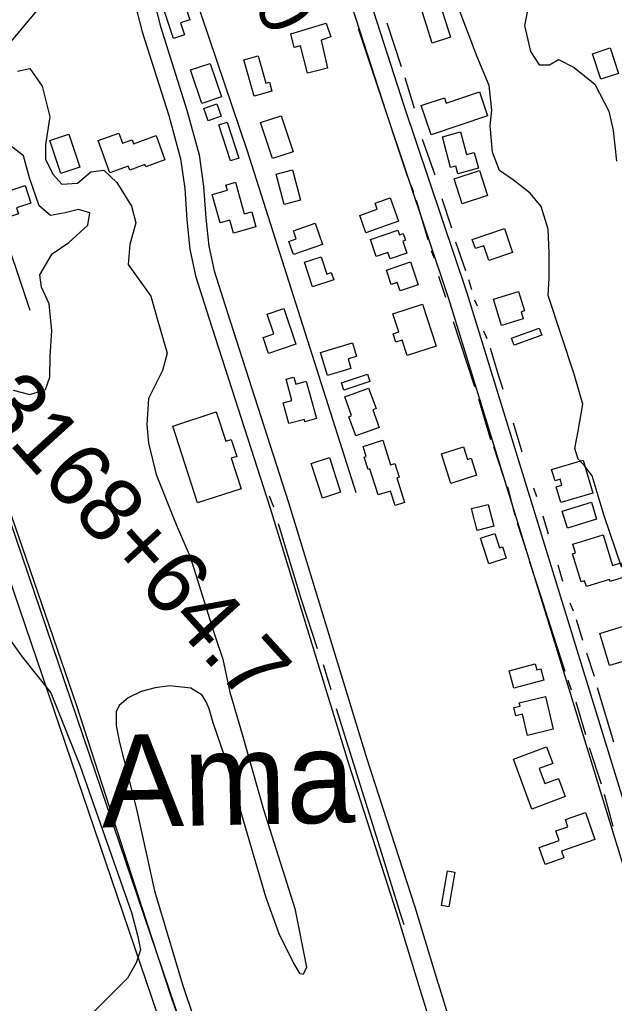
# Model space of a CAD drawing. Extents: x 3598634 to 3636690, y 517270 to 542944.
# Drawn here: x 3608244 to 3609179, y 527023 to 528569 of the extents above; entities that cross this region are included whole.
import ezdxf

# ---------------------------------------------------------------- set-up
doc = ezdxf.new("R2010")
doc.units = 0
for name, color, linetype in [('V-BLDG-OTLN', 7, 'Continuous'), ('V-RIVR-RANG-IDEN', 7, 'Continuous'), ('V-ROAD-CNTR', 7, 'Continuous'), ('V-SITE-VEGE', 7, 'Continuous'), ('V-SURV-IDEN', 7, 'Continuous'), ('V-TOPO-GNAM-IDEN', 7, 'Continuous'), ('V-TOPO-SHOR', 7, 'Continuous')]:
    doc.layers.add(name, color=color, linetype=linetype)

msp = doc.modelspace()

# ---------------------------------------------------------------- linework, layer by layer
at = {"layer": 'V-BLDG-OTLN'}
for points in [[(3608489.2, 528634.6), (3608511.4, 528568.5), (3608496.9, 528563.6), (3608503.1, 528545), (3608485.9, 528539.2), (3608455.8, 528628.5), (3608475.9, 528635.3), (3608477.5, 528630.7)], [(3608892.4, 528531.9), (3608871.5, 528598), (3608900.1, 528607), (3608921, 528540.9)], [(3608696.3, 528484.4), (3608685.5, 528527.3), (3608675.5, 528524.8), (3608670.1, 528546.1), (3608725.8, 528563.3), (3608733.2, 528541.5), (3608717.9, 528536.6), (3608728, 528492.4)], [(3609157.8, 528474.9), (3609144.3, 528515.1), (3609172, 528524.4), (3609185.5, 528484.2)], [(3608618.8, 528511.7), (3608631, 528468.8), (3608636.4, 528470.3), (3608640.4, 528456), (3608612.7, 528448.2), (3608596.5, 528505.4)], [(3608530.1, 528437.1), (3608512.6, 528489.5), (3608543.4, 528499.8), (3608560.9, 528447.4)], [(3608979.2, 528417.3), (3608890.7, 528387.6), (3608875.3, 528433.5), (3608911.8, 528445.8), (3608914.5, 528437.6), (3608966.6, 528455.1)], [(3608560.7, 528417.2), (3608540.3, 528409.8), (3608533.3, 528428.9), (3608553.8, 528436.4)], [(3608641.5, 528350.3), (3608622.6, 528406.8), (3608654.9, 528417.6), (3608673.8, 528361.1)], [(3608570.2, 528407.7), (3608588.4, 528351.1), (3608575.1, 528346.8), (3608556.9, 528403.4)], [(3608321, 528388.7), (3608338.6, 528336.8), (3608308.8, 528326.7), (3608291.2, 528378.6)], [(3608472, 528348.1), (3608442, 528337.2), (3608440.7, 528340.9), (3608416.8, 528332.3), (3608414.6, 528338.2), (3608385.6, 528327.7), (3608367.2, 528378.7), (3608399.6, 528390.4), (3608405.4, 528374.4), (3608420.5, 528379.8), (3608422.6, 528373.7), (3608458.2, 528386.5)], [(3608937, 528392.2), (3608946.4, 528356.8), (3608958.5, 528360), (3608965.1, 528335.2), (3608932.6, 528326.6), (3608929.4, 528338.5), (3608921.4, 528336.4), (3608908.5, 528384.7)], [(3608659.7, 528278.1), (3608646.9, 528325.8), (3608672.6, 528332.7), (3608685.4, 528285)], [(3608979.6, 528292.1), (3608939.4, 528279.2), (3608926.8, 528318.6), (3608967, 528331.4)], [(3608220.9, 528256.5), (3608208.1, 528296.9), (3608229.7, 528303.8), (3608230.6, 528300.9), (3608252.4, 528307.9), (3608261.3, 528280.1), (3608238.9, 528273), (3608242, 528263.3)], [(3608582.9, 528313), (3608597, 528263.3), (3608608.6, 528266.6), (3608615.3, 528243.3), (3608580.2, 528233.3), (3608574.4, 528253.8), (3608559, 528249.4), (3608546.4, 528293.7), (3608570.4, 528300.6), (3608568, 528308.8)], [(3608839.3, 528251.9), (3608788.2, 528233.7), (3608778.5, 528260.9), (3608805.8, 528270.7), (3608802.5, 528280), (3608826.2, 528288.5)], [(3608708.6, 528248.7), (3608720.1, 528215.3), (3608674.2, 528199.5), (3608667.1, 528220.2), (3608678.8, 528224.2), (3608674.5, 528236.9)], [(3608795.6, 528223.4), (3608838.5, 528237.6), (3608840.9, 528230.4), (3608847, 528232.5), (3608850.5, 528221.9), (3608846.5, 528220.5), (3608852.7, 528201.5), (3608826.2, 528192.7), (3608822.9, 528202.5), (3608804.5, 528196.5)], [(3608955.5, 528223.4), (3609006, 528240.3), (3609018.6, 528202.5), (3608981.3, 528190), (3608973.4, 528213.4), (3608960.3, 528209)], [(3608704.3, 528148.6), (3608691.4, 528187.5), (3608717.6, 528196.1), (3608726.6, 528168.7), (3608733.8, 528171.1), (3608737.6, 528159.6)], [(3608858.1, 528187.9), (3608870.3, 528151.8), (3608842.2, 528142.3), (3608837.6, 528155.7), (3608828.1, 528152.5), (3608820.5, 528175.2)], [(3609001.4, 528087.8), (3608988.6, 528129.4), (3609027.9, 528141.5), (3609037.3, 528111), (3609032.1, 528109.4), (3609035.6, 528098.3)], [(3608659.2, 528114.7), (3608678.1, 528058.8), (3608634.9, 528044.2), (3608626.4, 528069.4), (3608643.3, 528075.1), (3608632.9, 528105.8)], [(3608877, 528121.8), (3608898.6, 528055.7), (3608853, 528040.8), (3608845, 528065.2), (3608835.1, 528062), (3608830.8, 528075.2), (3608839.7, 528078.2), (3608830.5, 528106.6)], [(3609064.7, 528072.7), (3609021.1, 528057.1), (3609017.1, 528068.2), (3609060.7, 528083.8)], [(3608727.7, 528009.7), (3608716.9, 528045.8), (3608767, 528060.8), (3608773.4, 528039.5), (3608760.2, 528035.6), (3608764.6, 528020.7)], [(3608694.3, 528000.5), (3608710.4, 527941.9), (3608692.4, 527936.9), (3608691.4, 527940.6), (3608667.2, 527933.9), (3608658.2, 527966.7), (3608671.8, 527970.4), (3608662.6, 528003.5), (3608675, 528007), (3608678.1, 527996)], [(3608794.4, 528000), (3608753.5, 527986.5), (3608749.7, 527997.9), (3608790.6, 528011.4)], [(3608809.1, 527928), (3608772.3, 527914.5), (3608761.2, 527944.8), (3608765.8, 527946.5), (3608754.9, 527976.1), (3608792.2, 527989.8), (3608804.1, 527957.4), (3608799, 527955.5)], [(3608523.6, 527809.4), (3608484.4, 527930.1), (3608552.8, 527952.2), (3608567.7, 527906.3), (3608576.4, 527909.1), (3608585, 527882.4), (3608576.4, 527879.6), (3608591.9, 527831.6)], [(3608807.4, 527821.8), (3608794.6, 527862.7), (3608791.5, 527861.7), (3608785.4, 527881.2), (3608788.8, 527882.3), (3608783.8, 527898.1), (3608814.8, 527907.8), (3608827, 527869.1), (3608833.7, 527871.2), (3608840.4, 527850), (3608836.6, 527848.8), (3608848.9, 527809.7), (3608834.2, 527805.1), (3608827.1, 527828)], [(3608921.8, 527839.9), (3608907, 527886.2), (3608941.6, 527897.3), (3608947.9, 527877.7), (3608953.6, 527879.6), (3608962.2, 527852.8)], [(3608730.7, 527880.6), (3608748.2, 527826.1), (3608719.7, 527816.9), (3608702.2, 527871.4)], [(3609145, 527824.7), (3609094.6, 527809.8), (3609087.3, 527834.6), (3609096.2, 527837.2), (3609093.5, 527846.4), (3609085.5, 527844.1), (3609080.2, 527862), (3609129.7, 527876.6)], [(3608963.1, 527766.2), (3608954.4, 527800.3), (3608980.3, 527807), (3608989.1, 527772.9)], [(3609151, 527783.8), (3609105.4, 527769.6), (3609097, 527796.4), (3609142.7, 527810.6)], [(3608981.4, 527713.8), (3608968.5, 527754), (3608990.9, 527761.1), (3608998.1, 527738.6), (3609003, 527740.1), (3609008.7, 527722.5)], [(3609161.1, 527759.3), (3609176, 527710.9), (3609188.9, 527714.9), (3609195.7, 527692.9), (3609172.3, 527685.7), (3609171.3, 527689.2), (3609134.8, 527678), (3609132, 527687.1), (3609126.4, 527685.4), (3609112.8, 527729.5), (3609117.5, 527730.9), (3609113.3, 527744.6)], [(3609171.4, 527553.7), (3609155.9, 527604.1), (3609194.6, 527616), (3609210.1, 527565.6)], [(3609013.5, 527545.6), (3609054.4, 527556.3), (3609056.9, 527547.1), (3609063.1, 527548.7), (3609067.8, 527530.9), (3609020.7, 527518.4)], [(3609042.5, 527444.1), (3609034.5, 527477.4), (3609023.9, 527474.9), (3609020.8, 527487.7), (3609030.6, 527490.1), (3609029.4, 527495.4), (3609070.3, 527505.3), (3609082.7, 527453.8)], [(3609049, 527328.3), (3609020, 527406.7), (3609072.3, 527426.1), (3609081.9, 527400.1), (3609060.5, 527392.2), (3609069.3, 527368.4), (3609091, 527376.4), (3609101.5, 527347.8)], [(3609148.2, 527280.4), (3609095.8, 527262.2), (3609099.5, 527251.6), (3609069.8, 527241.3), (3609060.5, 527268.1), (3609091.9, 527279.1), (3609086.8, 527293.9), (3609105.8, 527300.5), (3609101.9, 527311.8), (3609133.5, 527322.8)], [(3608928.2, 527228.9), (3608918.6, 527174.7), (3608907, 527176.8), (3608916.6, 527231)]]:
    msp.add_lwpolyline(points, close=True, dxfattribs=at)
at = {"layer": 'V-ROAD-CNTR'}
for points in [[(3606832.7, 526952), (3606973.8, 527100.2), (3607148.9, 527293), (3607268.5, 527428.8), (3607385.5, 527558.8), (3607495.8, 527683.5), (3607551.8, 527751.4), (3607615.9, 527832.2), (3607705.6, 527929.3), (3607806.9, 528046.9), (3607941.6, 528200.2), (3608081.9, 528357.7), (3608279.1, 528592.5), (3608364.5, 528689.3), (3608525, 528869.3), (3608605.5, 528959.8), (3608701.5, 529074.5), (3608833.1, 529225.4), (3608919, 529316.1), (3609050.5, 529472.9), (3609139.7, 529575.2), (3609208.8, 529647.9)], [(3608665.2, 529018.6), (3608688, 528947.3), (3608746.2, 528749.1), (3608848.5, 528432), (3608946.8, 528139.6), (3609111.4, 527605.9), (3609243, 527178.6), (3609394.6, 526698), (3609572.4, 526137.8), (3609769.5, 525515.2), (3610214.2, 524114.9)], [(3608636.6, 529009.4), (3608659.4, 528938.5), (3608717.5, 528740.2), (3608820.1, 528422.7), (3608918.3, 528130.4), (3609082.7, 527597.1), (3609214.4, 527169.6), (3609366, 526689), (3609543.8, 526128.7), (3609740.9, 525506.2), (3610185.6, 524105.8)], [(3608466.5, 528803.7), (3608505.7, 528646.3), (3608601.7, 528362.3), (3608772.5, 527825.5)], [(3608387, 528725.9), (3608405.8, 528667.7), (3608436.5, 528549.6), (3608478.2, 528418.1), (3608496.5, 528349.9), (3608503.3, 528303.4), (3608506.7, 528254.2), (3608511.6, 528208.2), (3608520.5, 528166.1), (3608541.3, 528100.2), (3608637.9, 527800.8), (3608761.2, 527398.4), (3608836.5, 527165.4), (3608873.2, 527045.2)], [(3608415.5, 528735.2), (3608434.7, 528676.1), (3608465.4, 528557.9), (3608506.9, 528426.5), (3608526, 528356), (3608533.1, 528306.6), (3608536.6, 528256.8), (3608541.2, 528212.9), (3608549.6, 528173.8), (3608569.9, 528109.3), (3608666.5, 527809.8), (3608789.8, 527407.4), (3608865.1, 527174.4), (3608901.9, 527053.9)], [(3608142.4, 528423.1), (3608166, 528387.7), (3608205, 528272.8), (3608238.4, 528176.5), (3608259.9, 528112)], [(3608054.2, 528314.4), (3608072.5, 528248.4), (3608123.1, 528099.6), (3608208.2, 527838.6), (3608669.6, 526482.9)], [(3608025.3, 528306.3), (3608043.9, 528239.6), (3608094.6, 528090.1), (3608179.7, 527829.1), (3608641.1, 526473.6)], [(3608873.2, 527045.1), (3608939.5, 526829.9), (3609009.1, 526639.7), (3609044.2, 526629.2), (3609080.2, 526628), (3609104.6, 526627), (3609121.6, 526592.1), (3609230.3, 526240.8), (3609440, 525585.1), (3609623.7, 524999.7), (3609832.7, 524343), (3609927.9, 524054.3)], [(3608901.9, 527054), (3608968, 526839.5), (3609032.1, 526664.1), (3609049.1, 526659.1), (3609081.3, 526657.9), (3609123.7, 526656.3), (3609149.6, 526603.2), (3609259, 526249.8), (3609468.6, 525594.1), (3609652.3, 525008.8), (3609861.3, 524352.2), (3609956.4, 524063.6)]]:
    msp.add_lwpolyline(points, dxfattribs=at)
at = {"layer": 'V-SITE-VEGE'}
for points in [[(3609190.1, 527709), (3609162.9, 527788.8), (3609143.8, 527852), (3609131.5, 527868.5), (3609121.9, 527878.2), (3609116.5, 527894.7), (3609122.1, 527922.1), (3609129.1, 527964.7), (3609115.5, 528011.4), (3609074.6, 528135.1), (3609076.1, 528162.6), (3609076.2, 528202.4), (3609074.9, 528239.5), (3609064, 528275.2), (3609046.2, 528295.9), (3609020.2, 528316.5), (3608998.3, 528331.7), (3608987.4, 528360.6), (3608983.4, 528401.8), (3608986.2, 528426.5), (3608982.2, 528465), (3608963.1, 528510.3), (3608930.4, 528595.6)], [(3609041.5, 528580.1), (3609037.4, 528559.6), (3609046.9, 528518.3), (3609060.5, 528497.7), (3609077, 528497.6), (3609090.8, 528505.8), (3609115.5, 528493.4), (3609148.3, 528467.2), (3609170.2, 528424.6), (3609177, 528394.4), (3609182.3, 528346.3)], [(3608240.6, 528487.7), (3608259.9, 528491.7), (3608279, 528464.2), (3608291.2, 528416.1), (3608284.3, 528372.2), (3608284.2, 528348.8), (3608296.5, 528325.5), (3608310.2, 528310.3), (3608334.9, 528311.6), (3608355.5, 528329.4), (3608376.2, 528332.1), (3608396.7, 528312.8), (3608419.9, 528275.7), (3608426.7, 528249.6), (3608417, 528215.2), (3608414.2, 528183.7), (3608449.8, 528134.1), (3608460.6, 528097), (3608475.6, 528044.8), (3608468.6, 528017.3), (3608446.5, 527973.5), (3608443.7, 527932.3), (3608446.4, 527903.4), (3608458.6, 527853.9), (3608489.9, 527775.6), (3608511.8, 527724.7), (3608551.2, 527599.6), (3608563.5, 527563.9), (3608574.3, 527511.7)], [(3608233.7, 527986.4), (3608259.8, 527979.5), (3608284.5, 527987.7), (3608291.5, 528006.9), (3608291.6, 528039.8), (3608294.4, 528079.6), (3608290.4, 528122.2), (3608278.1, 528148.3), (3608275.4, 528167.6), (3608294.8, 528200.5), (3608320.9, 528218.3), (3608351.2, 528245.6), (3608354, 528264.9), (3608336.2, 528270.4), (3608315.5, 528265), (3608292.2, 528260.9), (3608274.4, 528276.1), (3608259.4, 528320.1), (3608249.9, 528354.4), (3608226.6, 528372.3)], [(3608513.4, 526943.8), (3608482.5, 527032), (3608442.8, 527153.6), (3608333.9, 527490.4), (3608248.1, 527739.2), (3608193.6, 527895.9)], [(3608224.4, 527600.5), (3608247.6, 527567.5), (3608292.8, 527511.1), (3608339.2, 527395.6), (3608419.5, 527166)], [(3608676.4, 527172.2), (3608695, 527079.6), (3608689.3, 527068.5), (3608684.9, 527069.6), (3608673.8, 527087.5), (3608651.7, 527132.1), (3608630.7, 527190.2), (3608566.9, 527408.8), (3608548.2, 527463.5), (3608541.6, 527485.8), (3608537.2, 527497), (3608530.5, 527507), (3608512.7, 527518.3), (3608479.3, 527521.7), (3608457, 527518.5), (3608434.7, 527513), (3608414.6, 527503), (3608400.1, 527490.8), (3608395.6, 527480.8), (3608395.5, 527459.6), (3608401, 527432.9), (3608427.3, 527328), (3608455.8, 527199.7), (3608499.8, 527052.5), (3608570.4, 526842.7)], [(3608574.3, 527511.7), (3608593.4, 527445.7), (3608627.4, 527327.5), (3608676.4, 527172.2)], [(3608419.5, 527166), (3608429.4, 527128.1), (3608433.8, 527106.9), (3608427, 527086.9), (3608413.6, 527062.4), (3608353.2, 527002.5)]]:
    msp.add_lwpolyline(points, dxfattribs=at)
at = {"layer": 'V-TOPO-SHOR'}
for p, q in [((3608821, 528563.4), (3608843.6, 528495.2)), ((3608849.2, 528477.6), (3608864, 528429.7)), ((3608876.6, 528380.8), (3608896.7, 528325)), ((3608859, 528308.9), (3608862.8, 528297.5)), ((3608867, 528285.1), (3608885.7, 528223.3)), ((3608907.8, 528287.5), (3608922.9, 528241.5)), ((3608929.2, 528219.4), (3608944.8, 528174.5)), ((3608890.8, 528206.1), (3608895.1, 528194.6)), ((3608902.4, 528165.5), (3608913.5, 528132.7)), ((3608949.5, 528160.2), (3608954.4, 528144.8)), ((3608959, 528128.6), (3608963.1, 528119.1)), ((3608925.2, 528094.4), (3608958.9, 527992.1)), ((3608973, 528079.6), (3608978.4, 528067.6)), ((3608965.2, 527972.7), (3608984, 527908.7)), ((3609019.5, 527935.3), (3609033.3, 527889.3)), ((3608988.7, 527898), (3609004, 527851.5)), ((3609010.6, 527834.7), (3609022.5, 527789.7)), ((3609051.9, 527832.8), (3609056.5, 527819.3)), ((3608636.3, 527820.4), (3608643, 527803)), ((3609066.2, 527789), (3609075, 527760.8)), ((3609026, 527777.9), (3609041.9, 527729.8)), ((3609089.8, 527711.8), (3609097.1, 527686.3)), ((3609108.8, 527652.5), (3609113.9, 527639.6)), ((3609118.8, 527625.9), (3609128.5, 527593.8)), ((3609135, 527573.7), (3609147.2, 527537.3)), ((3608721.2, 527555.6), (3608733.3, 527515.9)), ((3609105.8, 527530.9), (3609110.9, 527515.8)), ((3609152, 527519.1), (3609177.5, 527434.1)), ((3609118.1, 527496.7), (3609133.5, 527445.6)), ((3609139.1, 527424.9), (3609157.9, 527367.8)), ((3609162.8, 527351.5), (3609176.5, 527301.3))]:
    msp.add_line(p, q, dxfattribs=at)
for points in [[(3608776, 528554.8), (3608803.7, 528471.5), (3608853.4, 528321.6)], [(3608983.3, 528052.4), (3608996.7, 528009.2), (3609003.5, 527987.8)], [(3608650.3, 527777.1), (3608686.5, 527657.7), (3608711.3, 527580.4)], [(3609045.3, 527716.5), (3609062.6, 527663.6), (3609081.9, 527602.9), (3609100.8, 527544.8)], [(3608741.4, 527486.2), (3608779, 527365.6), (3608812.8, 527258.9), (3608841.8, 527164.1), (3608848, 527146.7)]]:
    msp.add_lwpolyline(points, dxfattribs=at)

# ---------------------------------------------------------------- texts
at = {"layer": 'V-RIVR-RANG-IDEN'}
msp.add_text('D-070', height=83, rotation=296.6054, dxfattribs=at).set_placement((3608503, 528809.8))
at = {"layer": 'V-SURV-IDEN'}
msp.add_text('3168+64.7', height=100, rotation=312.3006, dxfattribs=at).set_placement((3608175.2, 527957.8))
at = {"layer": 'V-TOPO-GNAM-IDEN'}
msp.add_text('Ama', height=145, rotation=1.1992, dxfattribs=at).set_placement((3608373.3, 527299.2))

doc.saveas('drawing.dxf')
